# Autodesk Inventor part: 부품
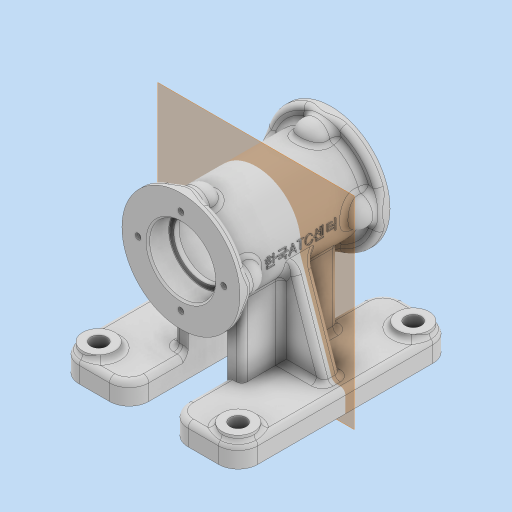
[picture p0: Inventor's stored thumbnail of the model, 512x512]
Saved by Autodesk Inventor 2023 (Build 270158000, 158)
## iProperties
Created: 2026-06
Part Number: 부품
Material: 일반
Document SubType Name: Modeling
Designer: home
Density: 1 g/cm^3
Appearance: 기본값
Author: home
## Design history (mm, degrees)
sketch "스케치1"
  geometry: L1 (50, 60)-(-50, 60); L2 (-50, 60)-(-50, -60); L3 (-50, -60)-(50, -60); L4 (50, -60)-(50, 60); L5 (50, 60)-(-50, -60); L6 (-50, 60)-(50, -60); 1 further point
  constraints: 12 end point, 2 midpoint, 2 parallel, 1 horizontal, 1 perpendicular
  dimensions: "d0" = 100 distance of L2.end L3.end; "d1" = 120 distance of L3.end L1.start
extrude "돌출1" new body sketch "스케치1" distance "d2" = 12; taper "d3" = 0 deg
sketch "스케치2"
  geometry: L1 (-11, 60)-(-11, -60); L2 (11, 60)-(11, -60); L3 (-50, 60)-(-50, -60) reference; L4 (50, -60)-(50, 60) reference; L5 (50, 60)-(-50, 60) reference; L6 (-11, 60)-(11, 60); L7 (-50, -60)-(50, -60) reference; L8 (-11, -60)-(11, -60); 1 further point
  constraints: 8 end point, 4 point on line, 2 vertical
  dimensions: "d4" = 39 distance between parallel lines of L1 L3; "d5" = 39 distance between parallel lines of L2 L4
extrude "돌출2" cut sketch "스케치2" extent not by distance; stored distance "d6" = 0; taper "d7" = 0 deg
node "작업 평면1"
node "작업 평면2"
sketch "스케치7"
  geometry: C1 r 33 at (0, 70); 1 further point
  constraints: 1 centre point, 1 vertical alignment
  dimensions: "d16" = 66 diameter of C1; "d17" = 70 distance of point (0, 0) C1.centre
extrude "돌출3" join sketch "스케치7" distance "d18" = 5; taper "d19" = 0 deg
sketch "스케치8"
  geometry: L1 (37, -37)-(103, -37) reference; L2 (37, 37)-(103, 37) reference; L3 (70, -37)-(70, 37); L4 (95, -37)-(95, 37); L5 (95, -37)-(70, -37); L6 (70, 37)-(70, -37); L7 (70, 37)-(95, 37); L8 (70, -37)-(70, 37); L9 (103, 42)-(37, 42) reference; 1 further point
  constraints: 12 end point, 3 collinear, 2 midpoint, 2 perpendicular, 2 point on line
  dimensions: "d20" = 50 diameter of L4 L3
revolve "회전2" sketch "스케치8" stored, may be unused: angle "d21" = 90 deg
sketch "스케치11"
  geometry: L1 (103, 42)-(37, 42) reference; L2 (88.5, 42)-(88.5, 30); L3 (88.5, 30)-(86, 30); L4 (86, 30)-(86, 27); L5 (86, 27)-(90, 27); L6 (90, 27)-(90, 0); L7 (95, -37)-(95, 37) reference; L8 (95, 0)-(37, 0); L9 (70, 42)-(70, -47.015); L10 (88.5, 42)-(70, 42); L11 (37, 37)-(103, 37) reference; L12 (70, 42)-(70, 0); L13 (70, 0)-(90, 0); 1 further point
  constraints: 20 end point, 5 perpendicular, 4 point on line, 2 midpoint, 1 collinear, 1 horizontal, 1 parallel, 1 vertical
  dimensions: "d22" = 32 diameter of L4 L9; "d23" = 37 diameter of L2 L9; "d24" = 12 distance of L2.start L2.end; "d25" = 27 distance of L5.end L6.end; "d26" = 40 diameter of L6 L9
revolve "회전3" sketch "스케치11" stored, may be unused: angle "d27" = 90 deg
fillet "모깎기1" dims "d28" = 11
sketch "스케치13"
  geometry: L1 (11, 27)-(19, 27); L2 (19, 27)-(19, -27); L3 (19, -27)-(11, -27); L4 (11, -27)-(11, 27); L5 (11, 49)-(11, -49) reference; 2 further points
  constraints: 8 end point, 2 midpoint, 2 parallel, 1 collinear, 1 horizontal, 1 perpendicular
  dimensions: "d32" = 54 distance of L3.end L1.start; "d41" = 8 distance between parallel lines of L2 L4
extrude "돌출4" join sketch "스케치13" stored distance "d34" = 5; taper "d35" = 0 deg; dims "d16" = 66, "d17" = 70
sketch "스케치14"
  geometry: L1 (24.587, 65.475)-(43, 12); L2 (19, 12)-(19, 53.752) reference; L3 (19, 12)-(19, 53.752); L4 (19, 12)-(43, 12); L5 (50, 12)-(50, 0) reference; A1 r 25 centre (0, 70) between (19, 53.752) and (19, 53.752) reference; A2 r 25 centre (0, 70) between (19, 53.752) and (24.587, 65.475); 2 further points
  constraints: 6 end point, 4 point on circle, 1 centre point, 1 coincident, 1 horizontal, 1 point on line
  dimensions: "d44" = 19 deg angle of L2 L1; "d45" = 7 distance from line of L1.end L5
extrude "돌출5" join sketch "스케치14" stored distance "d38" = 10; taper "d39" = 0 deg
fillet "모깎기3" dims "d40" = 3
sketch "스케치15"
  geometry: L1 (-39, -49)-(39, -49); L2 (39, -49)-(39, 49); L3 (39, 49)-(-39, 49); L4 (-39, 49)-(-39, -49); L5 (-39, -49)-(39, 49); L6 (39, -49)-(-39, 49); C1 r 9 at (-39, 49); C2 r 9 at (39, 49); C3 r 9 at (-39, -49); C4 r 9 at (39, -49); C5 r 4.5 at (-39, 49); C6 r 4.5 at (39, 49); C7 r 4.5 at (39, -49); C8 r 4.5 at (-39, -49); 1 further point
  constraints: 12 end point, 8 centre point, 8 coincident, 2 midpoint, 2 parallel, 1 horizontal, 1 perpendicular
  dimensions: "d46" = 78 distance of L2.end L3.end; "d47" = 98 distance of L3.end L1.start; "d48" = 18 diameter of C1; "d49" = 18 diameter of C2; "d50" = 18 diameter of C3; "d51" = 18 diameter of C4; "d54" = 9 diameter of C5; "d55" = 9 diameter of C6; "d56" = 9 diameter of C7; "d57" = 9 diameter of C8
extrude "돌출6" join sketch "스케치15" distance "d52" = 3; taper "d53" = 0 deg
feature "면 삭제1"
extrude "돌출7" cut sketch "스케치15" extent not by distance; stored distance "d58" = 0; taper "d59" = 0 deg
fillet "모깎기4" dims "d60" = 3
sketch "스케치16"
  geometry: C1 r 33 at (0, 0) reference; A1 r 24 centre (0, 0) between (-24, 0) and (0, -24); 3 further points
  constraints: 4 point on circle, 2 horizontal alignment, 2 vertical alignment, 1 centre point, 1 coincident
  dimensions: "d68" = 48 diameter of A1
hole "구멍1" sketch "스케치16" at (0, 24), (-24, 0), (0, -24), (24, 0) diameter "d61" = 3.242; stored, may be unused: countersink angle "d65" = 90 deg, drill point angle "d67" = 118 deg; dims "d62" = 8, "d63" = 4, "d64" = 2, "d66" = 10
sketch "스케치17"
  geometry: L1 (92.379, 42)-(95.621, 42) reference; L2 (94, 42)-(94, 29); L3 (94, 37)-(94, 19.967); C1 r 8 at (94, 32); 4 further points
  constraints: 4 end point, 2 point on line, 2 vertical, 1 centre point, 1 midpoint
  dimensions: "d75" = 16 diameter of C1; "d76" = 10 distance from line of C1.centre L1
revolve "회전4" sketch "스케치17" stored, may be unused: angle "d77" = 90 deg
fillet "모깎기5" dims "d83" = 3
sketch "스케치18"
  geometry: C1 r 18.5 at (0, 0) reference; C2 r 18.5 at (0, 0); 1 further point
  constraints: 1 centre point, 1 coincident, 1 concentric
extrude "돌출8" cut sketch "스케치18" stored distance "d78" = 10; taper "d79" = 0 deg
sketch "스케치22"
  geometry: C1 r 16 at (0, -24) reference; C2 r 20 at (0, -24); 1 further point
  constraints: 1 centre point, 1 coincident
  dimensions: "d85" = 40 diameter of C2
extrude "돌출9" cut sketch "스케치22" stored distance "d86" = 10; taper "d87" = 0 deg
sketch "스케치23"
  geometry: L1 (0, -49)-(0, 49) reference; 3 further points
  constraints: 1 horizontal alignment, 1 midpoint, 1 other
  dimensions: "d88" = 70 distance from line of point (70, 0) L1
feature "엠보싱1" sketch "스케치23" dims "d89" = 0.5, "d90" = 0
chamfer "모따기1" distance "d91" = 1; stored, may be unused: second distance "d92" = 2, angle "d93" = 45 deg
fillet "모깎기6" dims "d94" = 0.3
sketch "스케치24"
  geometry: L1 (-9, 20)-(8, 20); L2 (22, 52.679)-(22, 15) reference; L3 (-11, 14.196)-(-11, 47.55) reference; L4 (11, 14.196)-(11, 47.55) reference; L5 (-11, 48.629)-(11, 48.629); L6 (-11, 48.629)-(-11, 18); L7 (11, 48.629)-(11, 17); A1 r 25 centre (0, 70) between (9.508, 46.879) and (23.121, 60.492) reference; A2 r 25 centre (0, 70) between (-23.121, 60.492) and (-9.508, 46.879) reference; A3 r 2 centre (-9, 18) between (-9, 20) and (-11, 18); A4 r 3 centre (8, 17) between (11, 17) and (8, 20); 9 further points
  constraints: 8 end point, 4 point on circle, 3 point on line, 2 centre point, 2 tangent, 2 vertical, 1 horizontal, 1 horizontal alignment
  dimensions: "d95" = 20 distance from line of point (0, 0) L1; "d98" = 2 radius of A3 (derived); "d99" = 3 radius of A4 (derived)
extrude "돌출10" join sketch "스케치24" stored distance "d96" = 10; taper "d97" = 0 deg
fillet "모깎기7" dims "d100" = 3
node "솔리드1"
mirror "미러1"
mirror "미러2"
mirror "미러3"
mirror "미러4"
pattern_circular "원형 패턴1" dims angle "d81" = 360 deg
mirror "미러6"
mirror "미러7"
feature "A9D066F2-1C7D-4E18-AEED-F7BC21143FA4" dims "d61" = 3.242, "d62" = 8, "d63" = 4, "d64" = 2, "d65" = 90 deg, "d66" = 10, "d67" = 118 deg
other parameters: "d15" = 42
